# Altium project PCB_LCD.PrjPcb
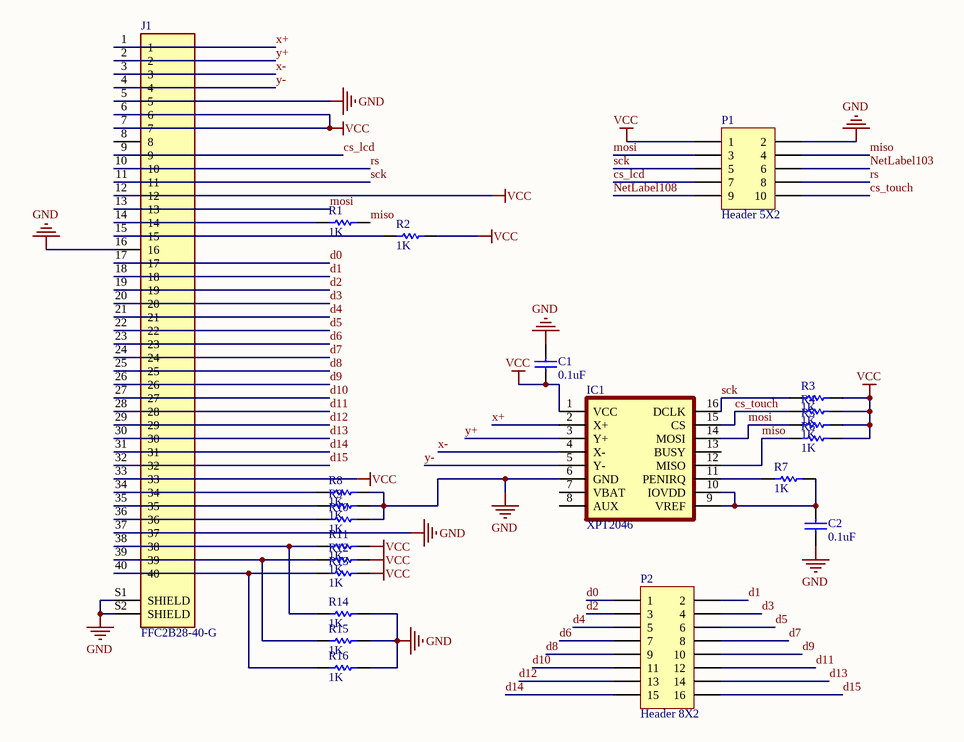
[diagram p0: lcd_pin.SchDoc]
1 sheet, 22 parts. Net scope: global (net labels, ports and power ports of the same name join across sheets).
Board file: pcb-lcd-cnc.PcbDoc

## Sheet lcd_pin.SchDoc
size A

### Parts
C1  0.1uF  [CAPC4817X12N]
C2  0.1uF  [CAPC4817X12N]
IC1  XPT2046  [TSSOP16]
J1  FFC2B28-40-G  [GCT_FFC2B28-40-G]
P1  Header 5X2  [HDR2X5]
P2  Header 8X2  [HDR2X8]
R1  1K  [RESC4817X04N]
R2  1K  [RESC4817X04N]
R3  1K  [RESC4817X04N]
R4  1K  [RESC4817X04N]
R5  1K  [RESC4817X04N]
R6  1K  [RESC4817X04N]
R7  1K  [RESC4817X04N]
R8  1K  [RESC4817X04N]
R9  1K  [RESC4817X04N]
R10  1K  [RESC4817X04N]
R11  1K  [RESC4817X04N]
R12  1K  [RESC4817X04N]
R13  1K  [RESC4817X04N]
R14  1K  [RESC4817X04N]
R15  1K  [RESC4817X04N]
R16  1K  [RESC4817X04N]

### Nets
GND: C1.2 C2.1 IC1.6(GND) J1.5 J1.16 J1.37 J1.S1(SHIELD) J1.S2(SHIELD) P1.2 R8.2 R9.2 R10.2 R14.2 R15.2 R16.2
VCC: C1.1 IC1.1(VCC) J1.6 J1.7 J1.12 J1.33 P1.1 R2.2 R3.2 R4.2 R5.2 R6.2 R11.2 R12.2 R13.2
cs_lcd: J1.9 P1.7
cs_touch: IC1.15(CS) P1.10 R4.1
d0: J1.17 P2.1
d1: J1.18 P2.2
d2: J1.19 P2.3
d3: J1.20 P2.4
d4: J1.21 P2.5
d5: J1.22 P2.6
d6: J1.23 P2.7
d7: J1.24 P2.8
d8: J1.25 P2.9
d9: J1.26 P2.10
d10: J1.27 P2.11
d11: J1.28 P2.12
d12: J1.29 P2.13
d13: J1.30 P2.14
d14: J1.31 P2.15
d15: J1.32 P2.16
miso: IC1.12(MISO) P1.4 R1.2 R6.1
mosi: IC1.14(MOSI) J1.13 P1.3 R5.1
NetLabel103: P1.6
NetLabel108: P1.9
rs: J1.10 P1.8
sck: IC1.16(DCLK) J1.11 P1.5 R3.1
x+: IC1.2(X+) J1.1
x-: IC1.4(X-) J1.3
y+: IC1.3(Y+) J1.2
y-: IC1.5(Y-) J1.4
NetC2_2: C2.2 IC1.9(VREF) IC1.10(IOVDD) R7.2
NetIC1_11: IC1.11(PENIRQ) R7.1
NetJ1_14: J1.14 R1.1
NetJ1_15: J1.15 R2.1
NetJ1_34: J1.34 R8.1
NetJ1_35: J1.35 R9.1
NetJ1_36: J1.36 R10.1
NetJ1_38: J1.38 R11.1 R14.1
NetJ1_39: J1.39 R12.1 R15.1
NetJ1_40: J1.40 R13.1 R16.1

Not connected (* = marked no-connect by the designer): IC1 7(VBAT) 8(AUX) 13(BUSY); J1 8

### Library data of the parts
C1 C2 = CAP SMD 1206: CAP 1206; Designer: Abbas Basereh
IC1 = XPT2046: RASPBERRY PI 3.5 TFT DISPLAY; MF: Xptek
J1 = FFC2B28-40-G: 40 Position FFC, FPC Connector Contacts, Top and Bottom 0.020 _0.50mm_ Surface Mount, Right Angle; MF: Global Connector Technology
P1 = Header 5X2: Header, 5-Pin, Dual row
P2 = Header 8X2: Header, 8-Pin, Dual row
R1-R16 = RES 1206 0.25W: RES 1206; Designer: Abbas Basereh; Desc.: RES SMD 1206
